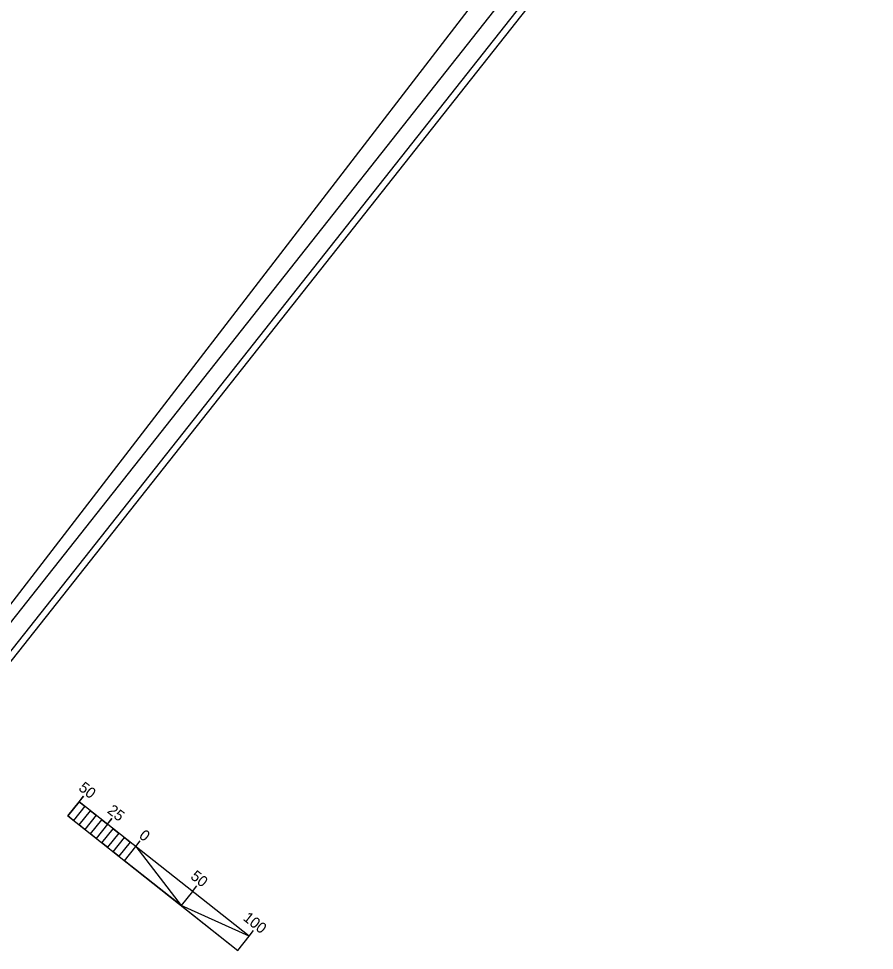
# Model space of a CAD drawing. Extents: x 556999 to 559002, y 505273 to 507273.
# Drawn here: x 558410 to 559002, y 505273 to 505917 of the extents above; entities that cross this region are included whole.
import ezdxf

# ---------------------------------------------------------------- set-up
doc = ezdxf.new("R2010")
doc.units = 0
for name, color, linetype in [('Prop Horizontal Alignment Direction Label', 7, 'Continuous'), ('Prop SS Cut Line', 7, 'Continuous'), ('Prop SS Fill Line', 7, 'Continuous'), ('Prop SS Transition Line', 7, 'Continuous'), ('Sheet Clip Boundary CELL', 7, 'Continuous'), ('Sheet Title CELL', 7, 'Continuous')]:
    doc.layers.add(name, color=color, linetype=linetype)

msp = doc.modelspace()

# ---------------------------------------------------------------- linework, layer by layer
at = {"layer": 'Prop Horizontal Alignment Direction Label'}
msp.add_lwpolyline([(559002.42, 506228.78), (557681.46, 507273.25), (556999.2, 506410.4), (558320.16, 505365.92)], close=True, dxfattribs=at)
at = {"layer": 'Prop SS Cut Line'}
msp.add_lwpolyline([(558973.57, 506219.71), (557796.95, 507150.06), (557145.7, 506326.43), (558322.33, 505396.07)], close=True, dxfattribs=at)
at = {"layer": 'Prop SS Fill Line'}
msp.add_lwpolyline([(558984.96, 506213.96), (557677.73, 507247.58), (557023.32, 506419.94), (558330.55, 505386.32)], close=True, dxfattribs=at)
at = {"layer": 'Prop SS Transition Line'}
for p, q in [((558451.92, 505375.47), (558455.02, 505379.38)), ((558471.53, 505359.96), (558474.63, 505363.88)), ((558530.37, 505313.45), (558533.46, 505317.37)), ((558569.59, 505282.44), (558572.7, 505286.37))]:
    msp.add_line(p, q, dxfattribs=at)
at = {"layer": 'Sheet Clip Boundary CELL'}
msp.add_lwpolyline([(558069.07, 506542.35), (558502.21, 506199.86), (558564.29, 506127.01), (558761.1, 505975.77), (558323.19, 505407.07), (558300.81, 505488.36), (558208.66, 505547.92), (558125.54, 505588.21), (558099.51, 505637.12), (558051.88, 505660.91), (558034.88, 505701.52), (557812.51, 505806.82), (557719.93, 505881.17), (557819.13, 505983.86), (557736.69, 506155.68), (557811.36, 506249.18), (557937.11, 506307.83), (558003.47, 506383.71), (558026.52, 506432.18), (558000.13, 506451.2)], close=True, dxfattribs=at)
at = {"layer": 'Sheet Title CELL'}
for p, q in [((558451.91, 505375.47), (558444.15, 505365.66)), ((558451.91, 505375.47), (558455, 505379.38)), ((558569.58, 505282.44), (558451.91, 505375.47)), ((558444.15, 505365.66), (558561.82, 505272.63)), ((558471.51, 505359.95), (558474.62, 505363.89)), ((558479.36, 505353.76), (558471.61, 505343.96)), ((558491.12, 505344.45), (558494.22, 505348.37)), ((558530.35, 505313.45), (558533.45, 505317.36)), ((558530.35, 505313.45), (558522.6, 505303.65)), ((558569.58, 505282.44), (558572.68, 505286.37)), ((558561.82, 505272.63), (558569.58, 505282.44))]:
    msp.add_line(p, q, dxfattribs=at)
for points in [[(558451.91, 505375.47), (558455.83, 505372.37), (558448.08, 505362.56), (558444.15, 505365.66)], [(558459.75, 505369.27), (558463.67, 505366.16), (558455.91, 505356.35), (558452, 505359.44)], [(558467.59, 505363.06), (558471.51, 505359.95), (558463.77, 505350.16), (558459.84, 505353.26)], [(558475.43, 505356.85), (558479.36, 505353.76), (558471.61, 505343.96), (558467.69, 505347.06)], [(558483.29, 505350.66), (558487.21, 505347.56), (558479.45, 505337.75), (558475.53, 505340.86)], [(558491.12, 505344.45), (558522.6, 505303.65), (558483.37, 505334.64)], [(558569.58, 505282.44), (558522.6, 505303.65), (558561.82, 505272.63)]]:
    msp.add_lwpolyline(points, close=True, dxfattribs=at)

# ---------------------------------------------------------------- texts
for s, p in [('50', (558450.95, 505384.05)), ('25', (558470.83, 505368.33)), ('0', (558492.78, 505350.98)), ('50', (558528.43, 505322.8)), ('100', (558564.78, 505294.06))]:
    msp.add_text(s, height=7.5, rotation=321.67144, dxfattribs=at).set_placement(p)

doc.saveas('drawing.dxf')
